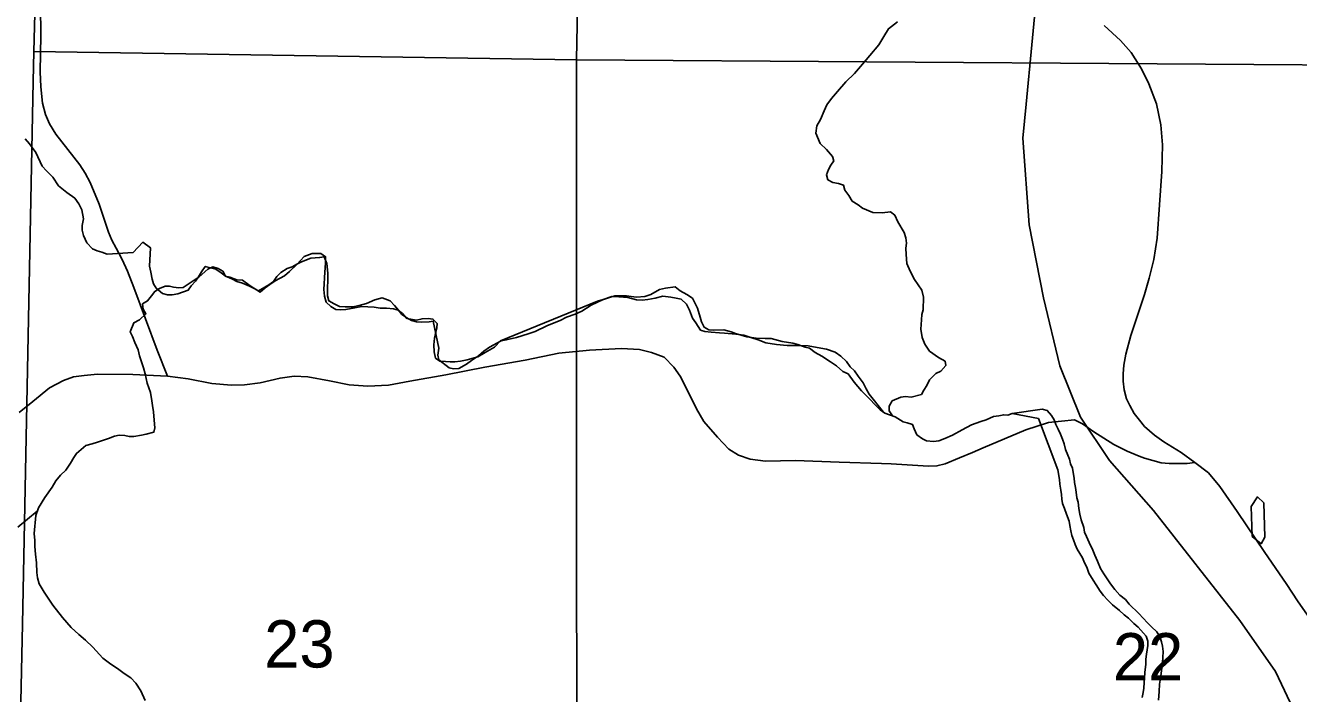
# Model space of a CAD drawing. Extents: x 0 to 34, y 0 to 22.
# Drawn here: x 4.51 to 5.636, y 16.807 to 17.398 of the extents above; entities that cross this region are included whole.
import ezdxf

# ---------------------------------------------------------------- set-up
doc = ezdxf.new("R2010")
doc.units = 0
for name, color, linetype in [('GM_X_Corporation', 7, 'Continuous'), ('GM_X_County_Road', 7, 'Continuous'), ('GM_X_Minor_Lake', 7, 'Continuous'), ('GM_X_Minor_River', 7, 'Continuous'), ('GM_X_Rail_Line', 7, 'Continuous'), ('GM_X_Section_Text', 7, 'Continuous'), ('GM_X_State_Route', 7, 'Continuous'), ('GM_X_Township_Road', 7, 'Continuous')]:
    doc.layers.add(name, color=color, linetype=linetype)

msp = doc.modelspace()

# ---------------------------------------------------------------- linework, layer by layer
at = {"layer": 'GM_X_Corporation'}
for points in [[(4.5438, 18.4054), (5.0167, 18.3983), (4.9971, 17.3675), (4.5169, 17.375), (4.5323, 17.9543)], [(5.0167, 18.3983), (6.0547, 18.3798), (6.0244, 17.3604), (4.9971, 17.3675)], [(4.5169, 17.375), (4.9971, 17.3675), (4.9974, 16.3535), (4.7398, 16.3567), (4.4961, 16.3597), (4.5069, 16.8684), (4.5165, 17.3484)], [(4.9971, 17.3675), (6.0244, 17.3604), (6.0014, 16.3259), (5.7595, 16.3331), (5.486, 16.3408), (5.2494, 16.3478), (4.9974, 16.3535)]]:
    msp.add_lwpolyline(points, close=True, dxfattribs=at)
at = {"layer": 'GM_X_County_Road'}
for points in [[(4.5039, 17.0554), (4.5161, 17.0654), (4.531, 17.0774), (4.5434, 17.0838), (4.5521, 17.0872), (4.5615, 17.0884), (4.5732, 17.0895), (4.6045, 17.0892), (4.6354, 17.0876), (4.6535, 17.0853), (4.6746, 17.0812), (4.692, 17.0797), (4.7035, 17.08), (4.7172, 17.0817), (4.7348, 17.086), (4.7472, 17.0877), (4.7594, 17.087), (4.7787, 17.0834), (4.796, 17.08), (4.8126, 17.0789), (4.8307, 17.0797), (4.8495, 17.0832), (4.8816, 17.0889), (4.9159, 17.0955), (4.9517, 17.1019), (4.9815, 17.1079), (5.0087, 17.1106), (5.0369, 17.1121), (5.0528, 17.1113), (5.0633, 17.1087), (5.0746, 17.1045), (5.0833, 17.0955), (5.0889, 17.0877), (5.0959, 17.0738), (5.1033, 17.0589), (5.1098, 17.0477), (5.1218, 17.0337), (5.1319, 17.0231), (5.1403, 17.0179), (5.1508, 17.0141), (5.1644, 17.0126), (5.1907, 17.013), (5.2295, 17.0117), (5.267, 17.0105), (5.2754, 17.01), (5.3085, 17.008), (5.3159, 17.0083), (5.3233, 17.0101), (5.3358, 17.0153), (5.3473, 17.0202)], [(5.3473, 17.0202), (5.3568, 17.0243), (5.3946, 17.0401), (5.4147, 17.0466), (5.4375, 17.049), (5.4446, 17.0456), (5.4547, 17.0384), (5.4724, 17.0272), (5.4841, 17.0212), (5.4948, 17.0169)], [(5.4948, 17.0169), (5.4997, 17.015), (5.5143, 17.0111), (5.5213, 17.0103), (5.5277, 17.0103), (5.5373, 17.0105), (5.5441, 17.0114)]]:
    msp.add_lwpolyline(points, dxfattribs=at)
at = {"layer": 'GM_X_Minor_Lake'}
for points in [[(5.6052, 16.9755), (5.5995, 16.9808), (5.5939, 16.9724), (5.5947, 16.9458)], [(5.5947, 16.9458), (5.6027, 16.9394), (5.6061, 16.9451), (5.6052, 16.9755)]]:
    msp.add_lwpolyline(points, dxfattribs=at)
at = {"layer": 'GM_X_Minor_River'}
msp.add_line((5.4057, 17.0501), (5.3824, 17.0547), dxfattribs=at)
for points in [[(5.2811, 17.4011), (5.2732, 17.395), (5.269, 17.3881), (5.2645, 17.3809), (5.2566, 17.3714), (5.2502, 17.3638), (5.243, 17.3555), (5.2354, 17.3479), (5.2279, 17.3395), (5.2226, 17.3334), (5.2184, 17.3277), (5.2162, 17.3224), (5.2128, 17.3148), (5.2098, 17.3091), (5.2087, 17.3027), (5.2125, 17.2936), (5.2182, 17.2883), (5.2235, 17.2819), (5.2246, 17.2781)], [(4.5092, 17.2977), (4.5133, 17.2932), (4.5187, 17.2856), (4.5244, 17.2735), (4.5282, 17.2693), (4.5339, 17.2637), (4.5388, 17.2561), (4.5461, 17.25), (4.5533, 17.2451), (4.5567, 17.2402), (4.5594, 17.2349), (4.5609, 17.2269), (4.5598, 17.2209), (4.5598, 17.2167), (4.561, 17.2121), (4.564, 17.2057), (4.5689, 17.2004), (4.5731, 17.1985), (4.5773, 17.1974), (4.5818, 17.1955), (4.605, 17.1971), (4.6133, 17.2062), (4.6201, 17.2013), (4.6194, 17.185), (4.6205, 17.1797), (4.6217, 17.1736), (4.6228, 17.1694), (4.6251, 17.1656), (4.6308, 17.1607), (4.6354, 17.1596), (4.6395, 17.1596), (4.6445, 17.1604), (4.6536, 17.1638), (4.6562, 17.1676), (4.66, 17.1718), (4.6626, 17.1756), (4.6653, 17.1801), (4.6687, 17.1847), (4.6781, 17.1824), (4.6827, 17.179)], [(5.2246, 17.2781), (5.222, 17.2743), (5.2201, 17.2705), (5.2182, 17.2659), (5.2194, 17.2614), (5.2239, 17.2591), (5.2289, 17.258), (5.2334, 17.2565), (5.2346, 17.2523), (5.238, 17.2474), (5.241, 17.2425), (5.2464, 17.2391), (5.2502, 17.2364), (5.2593, 17.2326), (5.2676, 17.2323), (5.2748, 17.233), (5.2786, 17.23), (5.2813, 17.2243), (5.287, 17.2149), (5.2885, 17.2099), (5.2889, 17.2054), (5.2885, 17.2008), (5.2886, 17.1952), (5.2893, 17.1872), (5.2924, 17.1807), (5.2962, 17.1732), (5.3027, 17.1637), (5.3042, 17.1576), (5.3039, 17.1463), (5.3027, 17.1421), (5.3024, 17.1375), (5.3016, 17.1292), (5.3028, 17.122), (5.3051, 17.1159), (5.3093, 17.1099), (5.3172, 17.1042), (5.3233, 17.1008), (5.3237, 17.097), (5.3195, 17.0921), (5.315, 17.0901), (5.3093, 17.0844), (5.3071, 17.0795), (5.3044, 17.0753), (5.3022, 17.0715), (5.2931, 17.0692), (5.2882, 17.0696), (5.284, 17.0692), (5.2764, 17.0658), (5.2738, 17.0612), (5.2738, 17.0571), (5.2765, 17.0526)], [(4.6827, 17.179), (4.6865, 17.176), (4.6922, 17.1737), (4.6967, 17.1715), (4.7017, 17.17), (4.7077, 17.1673), (4.7119, 17.1651), (4.7157, 17.1632), (4.7248, 17.1685), (4.7289, 17.1715), (4.732, 17.1757), (4.7354, 17.1795), (4.741, 17.183), (4.7456, 17.1845), (4.7497, 17.1868), (4.7539, 17.1887), (4.7622, 17.1921), (4.7698, 17.1925), (4.774, 17.1933), (4.7763, 17.1872), (4.777, 17.1789), (4.7771, 17.172), (4.7767, 17.166), (4.7767, 17.1588), (4.7779, 17.1542), (4.7828, 17.1516), (4.7874, 17.1493), (4.7923, 17.1489), (4.7991, 17.1489), (4.8048, 17.1501), (4.8112, 17.152), (4.8188, 17.1551), (4.8252, 17.157), (4.8321, 17.1543), (4.8362, 17.1502), (4.8397, 17.146), (4.8427, 17.1422), (4.8469, 17.1392), (4.8511, 17.1369), (4.8556, 17.1358), (4.8598, 17.1354), (4.8666, 17.1358), (4.8704, 17.1362), (4.8754, 17.1123), (4.8743, 17.1062), (4.8754, 17.1021), (4.8845, 17.0949), (4.8883, 17.0941), (4.8929, 17.0945), (4.8997, 17.0983), (4.9042, 17.1014), (4.9103, 17.1056), (4.9152, 17.1098), (4.9201, 17.1132), (4.9303, 17.1189), (4.9349, 17.1197), (4.9439, 17.122), (4.9542, 17.125), (4.9606, 17.1273), (4.9708, 17.1323), (4.9772, 17.1349), (4.9825, 17.1368), (4.9882, 17.1399), (4.9958, 17.1425), (5.0018, 17.1452), (5.0102, 17.1505), (5.02, 17.1551), (5.0264, 17.1574), (5.031, 17.1586), (5.0412, 17.1586), (5.0454, 17.1582), (5.0503, 17.1575), (5.0575, 17.1582), (5.0628, 17.1598), (5.0704, 17.1643), (5.0757, 17.1655), (5.0844, 17.1666), (5.0889, 17.1632), (5.0946, 17.1598), (5.0996, 17.1568), (5.1042, 17.1477), (5.1064, 17.1398), (5.1076, 17.1356), (5.1099, 17.131), (5.1141, 17.1288), (5.1182, 17.1284), (5.1273, 17.1288), (5.1338, 17.1269), (5.1376, 17.1254), (5.1429, 17.1239), (5.1478, 17.1224), (5.1561, 17.1213), (5.1641, 17.1209), (5.1694, 17.1209), (5.1789, 17.1183), (5.1884, 17.1168), (5.1929, 17.1157), (5.1994, 17.1134), (5.2032, 17.1123), (5.2081, 17.1085), (5.2142, 17.1055)], [(5.2686, 17.0558), (5.2559, 17.0718), (5.2533, 17.0764), (5.2506, 17.0817), (5.2464, 17.0877), (5.243, 17.0923), (5.2392, 17.096), (5.2358, 17.1006), (5.2308, 17.1055), (5.2259, 17.1089), (5.2183, 17.1116), (5.21, 17.1131), (5.202, 17.1146), (5.1937, 17.1149), (5.1834, 17.1149), (5.174, 17.1156), (5.1645, 17.1171), (5.1577, 17.1198), (5.1512, 17.122), (5.1451, 17.1239), (5.1379, 17.1247), (5.1281, 17.1258), (5.1235, 17.1261), (5.1163, 17.1265), (5.1107, 17.1272), (5.1069, 17.1284), (5.1027, 17.1348), (5.0996, 17.139), (5.097, 17.1462), (5.0943, 17.1515), (5.0897, 17.1557), (5.0852, 17.1568), (5.0806, 17.1575), (5.0734, 17.1583), (5.0666, 17.1567), (5.0602, 17.1556), (5.0552, 17.1548), (5.0503, 17.1552), (5.0424, 17.1574), (5.0344, 17.1578), (5.0283, 17.1582), (5.0208, 17.1555), (5.0158, 17.154), (4.9299, 17.1189), (4.9246, 17.1132), (4.9163, 17.1086), (4.9099, 17.1048), (4.9046, 17.1033), (4.9004, 17.1021), (4.8944, 17.101), (4.8894, 17.1002), (4.8853, 17.1002), (4.8811, 17.1006), (4.8762, 17.1009), (4.8724, 17.1036), (4.8712, 17.1093), (4.8708, 17.1153), (4.8716, 17.1214), (4.8727, 17.1267), (4.8734, 17.1305), (4.8738, 17.1343), (4.87, 17.1381), (4.8658, 17.1388), (4.8605, 17.1385), (4.8556, 17.1373), (4.8469, 17.1388), (4.8431, 17.143), (4.8393, 17.146), (4.8351, 17.1471), (4.829, 17.1479), (4.8234, 17.1479), (4.8181, 17.1486), (4.8124, 17.149), (4.8071, 17.1493), (4.801, 17.1482), (4.7931, 17.1467), (4.7881, 17.1463), (4.7843, 17.1466), (4.7798, 17.1493), (4.7756, 17.1531), (4.7741, 17.1584), (4.7737, 17.1644), (4.7744, 17.1796), (4.7751, 17.1876), (4.7751, 17.1933), (4.7709, 17.1963), (4.7633, 17.1963), (4.7562, 17.1936), (4.7497, 17.1864), (4.7433, 17.1803), (4.7388, 17.1765), (4.7305, 17.1719), (4.7259, 17.1689), (4.7218, 17.1658), (4.7172, 17.162), (4.7115, 17.1654), (4.7073, 17.1685), (4.7017, 17.1726), (4.6967, 17.173), (4.6903, 17.1753), (4.6865, 17.176)], [(4.6865, 17.176), (4.6842, 17.1805), (4.68, 17.1828), (4.6755, 17.1843), (4.6709, 17.1824), (4.6634, 17.1756), (4.6543, 17.1695), (4.649, 17.1661), (4.6452, 17.1657), (4.6407, 17.1664), (4.6369, 17.1672), (4.6331, 17.1672), (4.6282, 17.1653), (4.624, 17.1626), (4.621, 17.1588), (4.6176, 17.1542), (4.613, 17.1516), (4.6138, 17.147), (4.6161, 17.1428), (4.6104, 17.1375), (4.6055, 17.1349), (4.6021, 17.1269), (4.6044, 17.1227), (4.6063, 17.1174), (4.6094, 17.111), (4.6105, 17.1057), (4.6121, 17.1011), (4.614, 17.0951), (4.6155, 17.0897), (4.6174, 17.0814), (4.6201, 17.0731), (4.6213, 17.0659), (4.622, 17.0617), (4.6228, 17.056), (4.6236, 17.0488), (4.624, 17.042), (4.6232, 17.0382), (4.6164, 17.0363), (4.6123, 17.0355), (4.6054, 17.0343), (4.6013, 17.0343), (4.5975, 17.0351), (4.5926, 17.0355), (4.5884, 17.0347), (4.5831, 17.0324), (4.5732, 17.0293), (4.5687, 17.0278), (4.563, 17.0263), (4.5589, 17.0229), (4.5547, 17.0194), (4.5524, 17.0156), (4.5494, 17.0107), (4.5453, 17.0046), (4.5407, 17.0001), (4.5366, 16.9951), (4.5332, 16.9894), (4.5268, 16.9803), (4.5211, 16.9712), (4.5189, 16.9644), (4.5174, 16.9484), (4.5178, 16.9424), (4.5178, 16.937), (4.5186, 16.9302), (4.5194, 16.9226), (4.5198, 16.9139), (4.5202, 16.9094), (4.5217, 16.9041), (4.5263, 16.8965), (4.5339, 16.8851), (4.5423, 16.8741), (4.5499, 16.8654), (4.5567, 16.859), (4.5628, 16.8541), (4.5692, 16.848), (4.578, 16.8382), (4.5852, 16.8329), (4.5909, 16.8291), (4.597, 16.8246), (4.6027, 16.8208), (4.6072, 16.8162), (4.6118, 16.8094), (4.6156, 16.8007)], [(5.2142, 17.1055), (5.2218, 17.1002), (5.2271, 17.0968), (5.2328, 17.0919), (5.2373, 17.0896), (5.2427, 17.0824), (5.2491, 17.0748), (5.2563, 17.0676), (5.2617, 17.062), (5.2658, 17.0578), (5.27, 17.0548), (5.2791, 17.0518), (5.286, 17.0472), (5.2897, 17.0465), (5.2943, 17.045), (5.2958, 17.0412), (5.2981, 17.0359), (5.3031, 17.0321), (5.3068, 17.0306), (5.3129, 17.0298), (5.3175, 17.0306), (5.3228, 17.0325), (5.3296, 17.0356), (5.3383, 17.0401), (5.3466, 17.0447), (5.3549, 17.0477), (5.3595, 17.0489), (5.3659, 17.0519), (5.3708, 17.0527), (5.375, 17.0535), (5.3788, 17.0531), (5.3824, 17.0547)], [(5.3824, 17.0547), (5.4091, 17.0585), (5.4136, 17.0574), (5.4174, 17.0528), (5.4197, 17.049), (5.4212, 17.0449), (5.4231, 17.0407), (5.4254, 17.0365), (5.427, 17.032), (5.4285, 17.0278), (5.4296, 17.0229), (5.4316, 17.0179), (5.4331, 17.0142), (5.4342, 17.01), (5.4358, 17.0062), (5.4365, 17.0024), (5.4373, 16.9975), (5.4377, 16.9937), (5.4385, 16.9891), (5.4392, 16.985), (5.4396, 16.98), (5.4408, 16.9762), (5.4415, 16.9706), (5.4423, 16.9656), (5.4435, 16.9607), (5.4458, 16.9539), (5.4465, 16.9497), (5.4484, 16.9459), (5.4507, 16.9406), (5.4538, 16.9338), (5.4557, 16.9292), (5.458, 16.9239), (5.4606, 16.9175), (5.4637, 16.9129), (5.4664, 16.9084), (5.4694, 16.9039), (5.4732, 16.8989), (5.4778, 16.894), (5.4827, 16.8902), (5.4861, 16.8861), (5.4945, 16.8777), (5.5021, 16.8694), (5.5059, 16.866), (5.5105, 16.8615), (5.5127, 16.8577), (5.5146, 16.8527), (5.5154, 16.8489), (5.5162, 16.844), (5.5158, 16.8387), (5.5155, 16.8345), (5.514, 16.8224), (5.5129, 16.8152), (5.5125, 16.8087), (5.5121, 16.8011)], [(5.4057, 17.0501), (5.4229, 17.0047), (5.4244, 16.9963), (5.4248, 16.9921), (5.4256, 16.9868), (5.426, 16.983), (5.4264, 16.9789), (5.4271, 16.9751), (5.4287, 16.9705), (5.4306, 16.9656), (5.4329, 16.9595), (5.4336, 16.9557), (5.4344, 16.9508), (5.4352, 16.9466), (5.4367, 16.9429), (5.4382, 16.9387), (5.4401, 16.9345), (5.4447, 16.9269), (5.4466, 16.9224), (5.4485, 16.9186), (5.4504, 16.9133), (5.4542, 16.9072), (5.4569, 16.9031), (5.4603, 16.8974), (5.4634, 16.8936), (5.4672, 16.8894), (5.4714, 16.8853), (5.4774, 16.8804), (5.4816, 16.8766), (5.4854, 16.8735), (5.49, 16.869), (5.4941, 16.8656), (5.501, 16.8576), (5.5025, 16.8531), (5.5025, 16.8493), (5.5018, 16.8455), (5.5014, 16.8417), (5.5007, 16.8372), (5.5007, 16.833), (5.4999, 16.8254), (5.4996, 16.8205), (5.4992, 16.8167), (5.4989, 16.8117), (5.4985, 16.8079), (5.4974, 16.8034)], [(4.5201, 16.9682), (4.503, 16.9541)]]:
    msp.add_lwpolyline(points, dxfattribs=at)
at = {"layer": 'GM_X_Rail_Line'}
msp.add_lwpolyline([(5.6414, 16.7533), (5.6337, 16.7879), (5.6154, 16.8265), (5.5839, 16.8715), (5.5075, 16.9687), (5.4687, 17.0132), (5.443, 17.0513), (5.4247, 17.0968), (5.4102, 17.1571), (5.3976, 17.2214), (5.3918, 17.2983), (5.3948, 17.3282), (5.405, 17.4336), (5.4142, 17.5093), (5.4242, 17.5748), (5.4218, 17.6501), (5.4091, 17.6896), (5.3869, 17.7315), (5.3447, 17.7881), (5.2707, 17.8833), (5.0873, 18.104), (4.8515, 18.4096), (4.468, 18.9077)], dxfattribs=at)
at = {"layer": 'GM_X_State_Route'}
msp.add_lwpolyline([(5.6495, 16.8683), (5.6356, 16.8881), (5.6249, 16.9042), (5.6059, 16.9316), (5.5815, 16.9678), (5.5661, 16.99), (5.5562, 17.0021), (5.5441, 17.0114), (5.532, 17.02), (5.5166, 17.0296), (5.5084, 17.0354), (5.4997, 17.0432), (5.495, 17.0487), (5.4905, 17.0547), (5.4866, 17.0617), (5.4837, 17.0676), (5.4816, 17.0756), (5.4806, 17.0833), (5.4806, 17.0896), (5.4814, 17.0974), (5.4831, 17.1071), (5.4874, 17.1237), (5.4997, 17.16), (5.5038, 17.1744), (5.5078, 17.1909), (5.5107, 17.2098), (5.5148, 17.2687), (5.5155, 17.2924), (5.5141, 17.3101), (5.5102, 17.3285), (5.5033, 17.3462), (5.4968, 17.3594), (5.4877, 17.374), (5.4782, 17.3845), (5.464, 17.3979)], dxfattribs=at)
at = {"layer": 'GM_X_Township_Road'}
msp.add_lwpolyline([(4.5227, 17.4415), (4.5232, 17.3889), (4.5227, 17.3568), (4.5232, 17.3437), (4.5246, 17.3292), (4.5273, 17.319), (4.531, 17.311), (4.5365, 17.3017), (4.5471, 17.2881), (4.5578, 17.2745), (4.5624, 17.2672), (4.5668, 17.2591), (4.5747, 17.2399), (4.583, 17.215), (4.5861, 17.2081), (4.5898, 17.2008), (4.5951, 17.1909), (4.5999, 17.1807), (4.6056, 17.166), (4.626, 17.1106), (4.6354, 17.0876)], dxfattribs=at)

# ---------------------------------------------------------------- texts
at = {"layer": 'GM_X_Section_Text'}
for s, p in [('23', (4.7208, 16.8299)), ('22', (5.4716, 16.8185))]:
    msp.add_text(s, height=0.04186, rotation=0, dxfattribs=at).set_placement(p)

doc.saveas('drawing.dxf')
